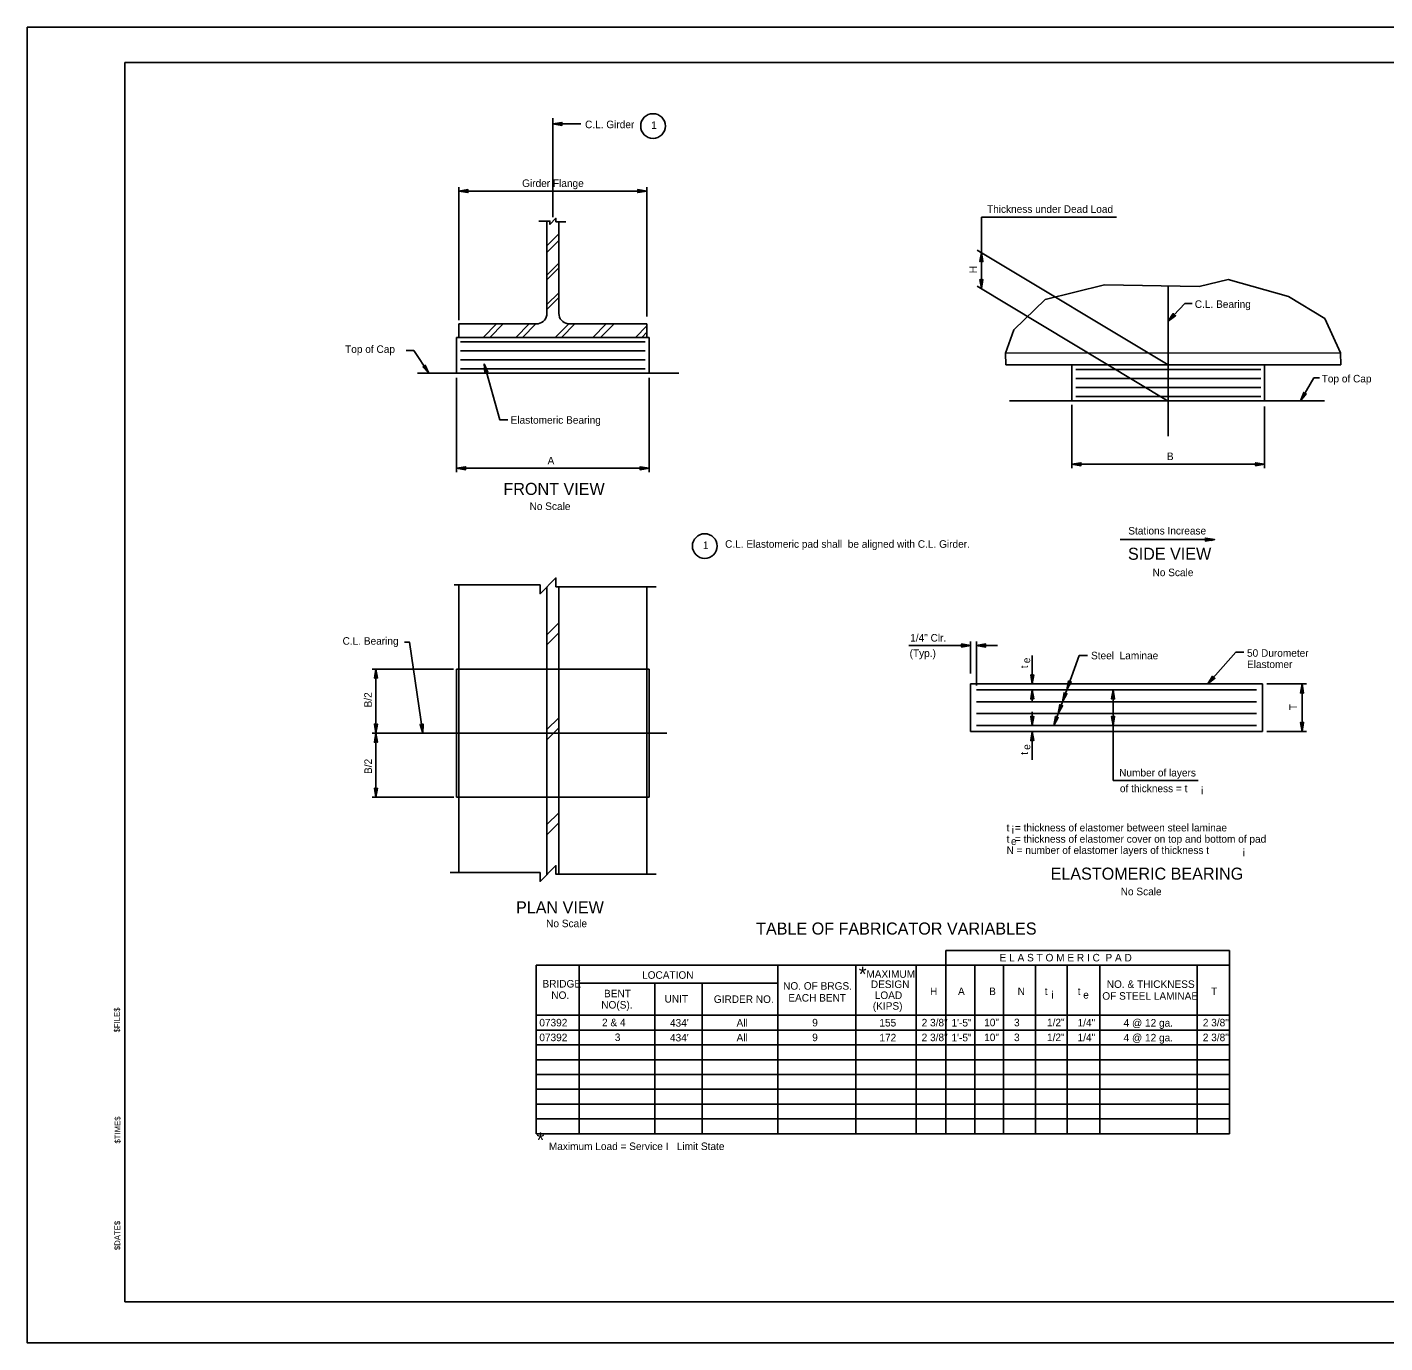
# Model space of a CAD drawing. Extents: x -193 to 149, y 507 to 725.
# Drawn here: x -192.5 to 32.6, y 507.1 to 725.2 of the extents above; entities that cross this region are included whole.
import ezdxf

# ---------------------------------------------------------------- set-up
doc = ezdxf.new("R2010")
doc.units = 0
for name, color, linetype in [('border', 7, 'Continuous'), ('Border 2660-Hwy18 - Level 62', 7, 'Continuous'), ('Dimensions', 7, 'Continuous'), ('Level 20', 7, 'Continuous'), ('Level 21', 7, 'Continuous'), ('Level 31', 7, 'Continuous'), ('Level 40', 7, 'Continuous'), ('Level 41', 7, 'Continuous'), ('Level 42', 7, 'Continuous'), ('Level 43', 7, 'Continuous'), ('Level 58', 7, 'Continuous')]:
    doc.layers.add(name, color=color, linetype=linetype)

# ---------------------------------------------------------------- blocks, each defined once
blk = doc.blocks.new('ARROW')
at = {"layer": 'Level 58'}
blk.add_lwpolyline([(-1.2, 0.251), (0, 0), (-1.2, -0.251), (-1.004, 0)], close=True, dxfattribs=at)

msp = doc.modelspace()

# ---------------------------------------------------------------- linework, layer by layer
at = {"layer": 'border'}
for p, q in [((-176.33, 719.31), (143.78, 719.31)), ((-176.33, 513.86), (-176.33, 719.31)), ((143.78, 513.86), (-176.33, 513.86))]:
    msp.add_line(p, q, dxfattribs=at)
at = {"layer": 'Border 2660-Hwy18 - Level 62'}
msp.add_lwpolyline([(-192.53, 725.17), (148.65, 725.17), (148.65, 507.07), (-192.53, 507.07)], close=True, dxfattribs=at)
at = {"layer": 'Dimensions'}
for p, q in [((-129.69, 671.58), (-128.41, 671.58)), ((-128.41, 671.58), (-125.92, 667.79))]:
    msp.add_line(p, q, dxfattribs=at)
msp.add_lwpolyline([(-125.92, 667.79), (-126.51, 669.12), (-126.64, 668.89), (-126.91, 668.86)], close=True, dxfattribs=at)
at = {"layer": 'Level 20'}
for p, q in [((-105.35, 693.67), (-105.35, 710.08)), ((-3.29, 657.38), (-3.29, 682.35)), ((-135.32, 608.13), (-86.47, 608.13))]:
    msp.add_line(p, q, dxfattribs=at)
at = {"layer": 'Level 21'}
for p, q in [((-84.47, 667.79), (-127.81, 667.79)), ((22.62, 663.21), (-29.62, 663.21))]:
    msp.add_line(p, q, dxfattribs=at)
at = {"layer": 'Level 31'}
for p, q in [((-106.33, 693.03), (-106.33, 677.74)), ((-104.36, 692.92), (-104.36, 677.74)), ((-107.8, 675.98), (-120.93, 675.98)), ((-120.93, 673.75), (-120.93, 675.98)), ((-102.89, 675.98), (-89.76, 675.98)), ((-89.76, 673.75), (-89.76, 675.98)), ((-121.33, 673.75), (-104.36, 673.75)), ((-121.33, 667.79), (-121.33, 673.75)), ((-89.37, 673.75), (-106.33, 673.75)), ((-89.37, 667.79), (-89.37, 673.75)), ((-120.68, 673.01), (-90.01, 673.01)), ((-120.68, 671.52), (-90.01, 671.52)), ((-30.3, 671.15), (25.29, 671.16)), ((-120.68, 670.02), (-90.01, 670.02)), ((-30.24, 669.17), (25.35, 669.19)), ((-19.27, 663.21), (-19.27, 669.17)), ((12.69, 663.21), (12.69, 669.17)), ((-120.68, 668.53), (-90.01, 668.53)), ((-18.62, 668.43), (12.05, 668.43)), ((-18.62, 666.94), (12.05, 666.94)), ((-18.62, 665.45), (12.05, 665.45)), ((-18.62, 663.95), (12.05, 663.95)), ((-120.93, 585.03), (-120.93, 632.7)), ((-106.33, 632.38), (-106.33, 584.69)), ((-104.36, 632.42), (-104.36, 584.74)), ((-89.76, 584.74), (-89.76, 632.42)), ((-121.33, 618.76), (-121.33, 597.5)), ((-120.93, 618.76), (-121.33, 618.76)), ((-120.93, 618.76), (-89.76, 618.76)), ((-89.76, 618.76), (-89.37, 618.76)), ((-89.37, 618.76), (-89.37, 597.5)), ((-36.07, 616.29), (12.33, 616.29)), ((-36.07, 616.29), (-36.07, 608.42)), ((-35.09, 615.31), (11.33, 615.31)), ((12.33, 616.29), (12.33, 608.42)), ((-35.09, 613.34), (-20.87, 613.34)), ((-20.87, 613.34), (11.33, 613.34)), ((-35.09, 611.37), (11.33, 611.37)), ((-36.07, 608.42), (12.33, 608.42)), ((-35.09, 609.4), (-22.31, 609.4)), ((-22.31, 609.4), (11.33, 609.4)), ((-120.93, 597.5), (-121.33, 597.5)), ((-120.93, 597.5), (-89.76, 597.5)), ((-89.76, 597.5), (-89.37, 597.5))]:
    msp.add_line(p, q, dxfattribs=at)
for centre, start, end in [((-108.1, 677.73), 279.5, 0), ((-102.59, 677.73), 180, 260.5)]:
    msp.add_arc(centre, 1.76, start, end, dxfattribs=at)
at = {"layer": 'Level 40'}
for p, q in [((-100.96, 569.66), (-100.96, 541.74)), ((-68.06, 569.66), (-68.06, 541.74)), ((-55.1, 569.66), (-55.1, 541.74)), ((-45.11, 569.66), (-45.11, 541.74)), ((-35.38, 569.66), (-35.38, 541.74)), ((-30.59, 569.66), (-30.59, 541.74)), ((-25.3, 569.66), (-25.3, 541.74)), ((-20.03, 569.66), (-20.03, 541.74)), ((-14.65, 569.66), (-14.65, 541.74)), ((1.49, 569.66), (1.49, 541.74)), ((-100.96, 566.68), (-68.06, 566.68)), ((-88.46, 566.68), (-88.46, 541.74)), ((-80.56, 566.68), (-80.56, 541.74)), ((-108.12, 561.37), (6.87, 561.37)), ((6.87, 561.87), (6.87, 558.38)), ((-108.12, 558.92), (6.87, 558.92)), ((-108.12, 556.46), (6.87, 556.46)), ((-108.12, 554.01), (6.87, 554.01)), ((-108.12, 551.56), (6.87, 551.56)), ((-108.12, 549.1), (6.87, 549.1)), ((-108.12, 546.65), (6.87, 546.65)), ((-108.12, 544.2), (6.87, 544.2))]:
    msp.add_line(p, q, dxfattribs=at)
for centre in [(-88.73, 708.78), (-80.15, 639.15)]:
    msp.add_circle(centre, 2.05, dxfattribs=at)
at = {"layer": 'Level 41'}
for p, q in [((-40.17, 572.11), (-40.17, 541.74)), ((-40.17, 572.11), (6.87, 572.11)), ((6.87, 572.11), (6.87, 541.74)), ((-108.12, 569.66), (6.87, 569.66)), ((-108.12, 569.66), (-108.12, 541.74)), ((-108.12, 541.74), (6.87, 541.74))]:
    msp.add_line(p, q, dxfattribs=at)
at = {"layer": 'Level 42'}
for p, q in [((-106.33, 688.92), (-104.36, 690.89)), ((-106.33, 687.82), (-104.36, 689.81)), ((-106.33, 684.07), (-104.36, 686.03)), ((-106.33, 683.3), (-104.36, 685.27)), ((-106.33, 679.18), (-104.36, 681.15)), ((-106.33, 678.37), (-104.36, 680.37)), ((-116.93, 673.75), (-114.7, 675.98)), ((-115.8, 673.75), (-113.57, 675.98)), ((-111.5, 673.75), (-109.28, 675.98)), ((-110.4, 673.75), (-108.18, 675.98)), ((-104.95, 673.75), (-102.71, 675.98)), ((-103.92, 673.75), (-101.69, 675.98)), ((-98.73, 673.75), (-96.52, 675.98)), ((-97.43, 673.75), (-95.2, 675.98)), ((-91.64, 673.75), (-89.76, 675.66)), ((-90.59, 673.75), (-89.76, 674.59)), ((-106.33, 624.46), (-104.36, 626.43)), ((-106.33, 622.79), (-104.36, 624.78)), ((-106.33, 608.72), (-104.36, 610.69)), ((-106.33, 607.04), (-104.36, 609.04)), ((-106.33, 592.98), (-104.36, 594.94)), ((-106.33, 591.3), (-104.36, 593.29))]:
    msp.add_line(p, q, dxfattribs=at)
at = {"layer": 'Level 43'}
for p, q in [((-100.7, 709.12), (-105.35, 709.12)), ((-120.93, 676.61), (-120.93, 698.64)), ((-89.76, 677.19), (-89.76, 698.64)), ((-120.93, 698), (-89.76, 698)), ((-11.84, 693.7), (-34.28, 693.7)), ((-34.28, 693.7), (-34.28, 691.97)), ((-34.28, 681.83), (-34.28, 691.97)), ((-3.29, 669.17), (-34.96, 688.23)), ((-3.29, 663.18), (-35, 682.26)), ((-121.33, 667.04), (-121.33, 651.4)), ((-89.37, 667.04), (-89.37, 651.4)), ((-19.27, 662.56), (-19.27, 652.06)), ((12.69, 662.31), (12.69, 652.06)), ((-121.33, 652.04), (-89.37, 652.04)), ((-19.27, 652.71), (12.69, 652.71)), ((-46.28, 622.67), (-36.07, 622.67)), ((-36.07, 618.02), (-36.07, 623.31)), ((-35.09, 616.05), (-35.09, 623.31)), ((-31.6, 622.67), (-35.09, 622.67)), ((-25.85, 621), (-25.85, 616.29)), ((-121.82, 618.76), (-135.32, 618.76)), ((-134.68, 608.13), (-134.68, 618.76)), ((-25.85, 615.31), (-25.85, 613.23)), ((-12.42, 607.44), (-12.42, 615.31)), ((13.06, 616.29), (19.66, 616.29)), ((18.91, 608.42), (18.91, 616.29)), ((-25.85, 609.4), (-25.85, 611.68)), ((-134.68, 597.5), (-134.68, 608.13)), ((-25.85, 603.73), (-25.85, 608.42)), ((13.06, 608.42), (19.66, 608.42)), ((-12.42, 607.44), (-12.42, 600.28)), ((-12.42, 600.28), (1.69, 600.28)), ((-121.79, 597.5), (-135.32, 597.5))]:
    msp.add_line(p, q, dxfattribs=at)
for points in [[(-105.35, 709.12), (-103.85, 708.87), (-103.98, 709.12), (-103.85, 709.37)], [(-120.93, 698), (-119.43, 697.75), (-119.56, 698), (-119.43, 698.25)], [(-89.76, 698), (-91.26, 698.25), (-91.13, 698), (-91.26, 697.75)], [(-34.28, 687.81), (-34.53, 686.31), (-34.28, 686.44), (-34.03, 686.31)], [(-34.28, 681.83), (-34.03, 683.33), (-34.28, 683.2), (-34.53, 683.33)], [(-3.29, 676.42), (-2.08, 677.34), (-2.35, 677.42), (-2.44, 677.68)], [(-116.74, 669.37), (-116.62, 667.86), (-116.41, 668.04), (-116.13, 667.98)], [(18.64, 663.21), (19.61, 664.37), (19.33, 664.39), (19.18, 664.63)], [(-121.33, 652.04), (-119.83, 651.79), (-119.96, 652.04), (-119.83, 652.29)], [(-89.37, 652.04), (-90.87, 652.29), (-90.74, 652.04), (-90.87, 651.79)], [(-19.27, 652.71), (-17.77, 652.46), (-17.9, 652.71), (-17.77, 652.96)], [(12.69, 652.71), (11.19, 652.96), (11.32, 652.71), (11.19, 652.46)], [(4.39, 640.22), (2.89, 640.47), (3.02, 640.22), (2.89, 639.97)], [(-36.07, 622.67), (-37.57, 622.92), (-37.44, 622.67), (-37.57, 622.42)], [(-35.09, 622.67), (-33.59, 622.42), (-33.72, 622.67), (-33.59, 622.92)], [(-134.68, 618.76), (-134.93, 617.26), (-134.68, 617.39), (-134.43, 617.26)], [(-25.85, 616.29), (-25.6, 617.79), (-25.85, 617.66), (-26.1, 617.79)], [(3.27, 616.29), (4.46, 617.25), (4.18, 617.32), (4.08, 617.58)], [(-25.85, 615.31), (-26.1, 613.81), (-25.85, 613.94), (-25.6, 613.81)], [(-20.84, 613.34), (-20.09, 614.66), (-20.37, 614.63), (-20.56, 614.83)], [(-20.12, 615.31), (-19.37, 616.63), (-19.65, 616.59), (-19.84, 616.8)], [(-12.42, 615.31), (-12.67, 613.81), (-12.42, 613.94), (-12.17, 613.81)], [(18.91, 616.29), (18.66, 614.79), (18.91, 614.92), (19.16, 614.79)], [(-21.56, 611.37), (-20.81, 612.69), (-21.09, 612.66), (-21.28, 612.87)], [(-25.85, 609.4), (-25.6, 610.9), (-25.85, 610.77), (-26.1, 610.9)], [(-22.28, 609.4), (-21.53, 610.73), (-21.81, 610.69), (-22, 610.9)], [(-12.42, 609.4), (-12.17, 610.9), (-12.42, 610.77), (-12.67, 610.9)], [(-134.68, 608.13), (-134.43, 609.63), (-134.68, 609.5), (-134.93, 609.63)], [(-134.68, 608.13), (-134.93, 606.63), (-134.68, 606.76), (-134.43, 606.63)], [(-126.9, 608.13), (-126.87, 609.65), (-127.09, 609.49), (-127.36, 609.58)], [(-25.85, 608.42), (-26.1, 606.92), (-25.85, 607.05), (-25.6, 606.92)], [(18.91, 608.42), (19.16, 609.92), (18.91, 609.79), (18.66, 609.92)], [(-134.68, 597.5), (-134.43, 599), (-134.68, 598.87), (-134.93, 599)]]:
    msp.add_lwpolyline(points, close=True, dxfattribs=at)
for points in [[(-107.66, 693.03), (-105.84, 693.03), (-105.84, 692.48), (-104.83, 693.49), (-104.83, 692.92), (-103.19, 692.92)], [(-30.24, 669.17), (-30.3, 671.13), (-28.92, 674.99), (-23.67, 680.04), (-13.85, 682.48), (1.87, 682.19), (6.66, 683.36), (16.66, 680.5), (22.71, 676.85), (25.29, 671.16), (25.35, 669.19)], [(0.68, 679.37), (-0.51, 679.37), (-3.29, 676.42)], [(-116.74, 669.37), (-114.12, 660.07), (-112.81, 660.06)], [(21.79, 667.02), (20.88, 667.02), (18.64, 663.21)], [(-11.26, 640.22), (4.39, 640.22)], [(-121.72, 632.7), (-107.46, 632.7), (-107.46, 631.26), (-104.83, 633.87), (-104.83, 632.42), (-88.23, 632.42)], [(-129.95, 623.21), (-129.11, 623.21), (-126.9, 608.13)], [(3.27, 616.29), (7.92, 621.54), (9.26, 621.54)], [(-20.12, 615.31), (-18.03, 621.01), (-16.69, 621.01)], [(-20.84, 613.34), (-20.12, 615.31)], [(-21.56, 611.37), (-20.84, 613.34)], [(-22.28, 609.4), (-21.56, 611.37)], [(-122.39, 585.03), (-107.46, 585.03), (-107.46, 583.57), (-104.83, 586.18), (-104.83, 584.74), (-88.23, 584.74)]]:
    msp.add_lwpolyline(points, dxfattribs=at)

# ---------------------------------------------------------------- block references
at = {"layer": 'Level 43', "xscale": 0.5247989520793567, "yscale": 0.5247989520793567}
msp.add_blockref('ARROW', (4.39, 640.22), dxfattribs=at)

# ---------------------------------------------------------------- texts
at = {"layer": 'border'}
for s, p in [('$FILE$', (-177.16, 558.52)), ('$TIME$', (-177.06, 540.11)), ('$DATE$', (-177.1, 522.44))]:
    msp.add_text(s, height=0.96, rotation=89.9999, dxfattribs=at).set_placement(p)
at = {"layer": 'Level 40'}
for s, height, p in [('C.L. Girder', 1.25, (-100.01, 708.42)), ('1', 1.25, (-89.04, 708.3)), ('Girder Flange', 1.25, (-110.44, 698.68)), ('Thickness under Dead Load', 1.25, (-33.34, 694.39)), ('C.L. Bearing', 1.25, (1.12, 678.63)), ('Top of Cap', 1.25, (-139.8, 671.17)), ('Top of Cap', 1.25, (22.16, 666.28)), ('Elastomeric Bearing', 1.25, (-112.35, 659.43)), ('A', 1.25, (-106.22, 652.69)), ('B', 1.25, (-3.51, 653.41)), ('No Scale', 1.25, (-109.21, 645.13)), ('Stations Increase', 1.25, (-9.91, 641.07)), ('1', 1.25, (-80.46, 638.66)), ('C.L. Elastomeric pad shall  be aligned with C.L. Girder.', 1.25, (-76.78, 638.87)), ('No Scale', 1.25, (-5.89, 634.16)), ('C.L. Bearing', 1.25, (-140.22, 622.8)), ('1/4" Clr.', 1.25, (-46.08, 623.32)), ('(Typ.)', 1.25, (-46.18, 620.77)), ('Steel  Laminae', 1.25, (-16.09, 620.38)), ('50 Durometer', 1.25, (9.78, 620.8)), ('Elastomer', 1.25, (9.78, 618.93)), ('Number of layers', 1.25, (-11.42, 600.96)), ('of thickness = t', 1.25, (-11.3, 598.35)), ('i', 1.25, (2.17, 597.99)), ('t  = thickness of elastomer between steel laminae', 1.25, (-30.1, 591.85)), ('i', 1.25, (-29.24, 591.47)), ('t  = thickness of elastomer cover on top and bottom of pad', 1.25, (-30.1, 589.98)), ('e', 1.25, (-29.36, 589.6)), ('N = number of elastomer layers of thickness t', 1.25, (-30.1, 588.12)), ('i', 1.25, (9.07, 587.72)), ('No Scale', 1.25, (-11.17, 581.27)), ('No Scale', 1.25, (-106.46, 575.97)), ('E L A S T O M E R I C  P A D', 1.25, (-31.25, 570.3)), ('LOCATION', 1.25, (-90.55, 567.42)), ('*', 2.5, (-54.62, 566.95)), ('MAXIMUM', 1.25, (-53.35, 567.59)), ('BRIDGE', 1.25, (-107.07, 565.97)), ('NO.', 1.25, (-105.6, 564.08)), ('BENT', 1.25, (-96.86, 564.35)), ('NO. OF BRGS.', 1.25, (-67.16, 565.61)), ('DESIGN', 1.25, (-52.61, 565.89)), ('LOAD', 1.25, (-51.96, 564.07)), ('H', 1.25, (-42.79, 564.72)), ('A', 1.25, (-38.15, 564.72)), ('B', 1.25, (-32.99, 564.72)), ('N', 1.25, (-28.26, 564.72)), ('t ', 1.25, (-23.76, 564.72)), ('i', 1.25, (-22.65, 564.14)), ('t ', 1.25, (-18.29, 564.72)), ('OF STEEL LAMINAE', 1.25, (-14.22, 563.95)), ('NO. & THICKNESS', 1.25, (-13.48, 565.91)), ('T', 1.25, (3.83, 564.72)), ('NO(S).', 1.25, (-97.32, 562.48)), ('UNIT', 1.25, (-86.82, 563.48)), ('GIRDER NO.', 1.25, (-78.65, 563.42)), ('EACH BENT', 1.25, (-66.29, 563.64)), ('(KIPS)', 1.25, (-52.28, 562.29)), ('e', 1.25, (-17.38, 564.14)), ('07392', 1.25, (-107.59, 559.53)), ('2 & 4', 1.25, (-97.19, 559.56)), ("434'", 1.25, (-85.92, 559.49)), ('All', 1.25, (-74.88, 559.49)), ('9', 1.25, (-62.33, 559.53)), ('155', 1.25, (-51.19, 559.51)), ('2 3/8"', 1.25, (-44.18, 559.53)), ('1\'-5"', 1.25, (-39.23, 559.51)), ('10"', 1.25, (-33.81, 559.55)), ('3', 1.25, (-28.86, 559.55)), ('1/2"', 1.25, (-23.39, 559.55)), ('1/4"', 1.25, (-18.32, 559.52)), ('4 @ 12 ga.', 1.25, (-10.69, 559.49)), ('2 3/8"', 1.25, (2.45, 559.53)), ('07392', 1.25, (-107.59, 557.08)), ('3', 1.25, (-95.07, 557.1)), ("434'", 1.25, (-85.92, 557.04)), ('All', 1.25, (-74.88, 557.04)), ('9', 1.25, (-62.33, 557.08)), ('172', 1.25, (-51.19, 557.05)), ('2 3/8"', 1.25, (-44.18, 557.08)), ('1\'-5"', 1.25, (-39.23, 557.05)), ('10"', 1.25, (-33.81, 557.09)), ('3', 1.25, (-28.86, 557.09)), ('1/2"', 1.25, (-23.39, 557.09)), ('1/4"', 1.25, (-18.32, 557.07)), ('4 @ 12 ga.', 1.25, (-10.69, 557.04)), ('2 3/8"', 1.25, (2.45, 557.08)), ('*', 2.5, (-108.05, 539.44)), ('Maximum Load = Service I   Limit State', 1.25, (-106.01, 539.03))]:
    msp.add_text(s, height=height, dxfattribs=at).set_placement(p)
for s, p in [('H', (-35.02, 684.37)), ('t', (-26.55, 618.9)), ('e', (-26.18, 619.73)), ('B/2', (-135.38, 612.41)), ('T', (18.06, 611.96)), ('e', (-26.16, 605.37)), ('B/2', (-135.35, 601.37)), ('t', (-26.53, 604.55))]:
    msp.add_text(s, height=1.25, rotation=90, dxfattribs=at).set_placement(p)
at = {"layer": 'Level 41'}
for s, p in [(' FRONT VIEW ', (-114.28, 647.63)), (' SIDE VIEW ', (-10.71, 636.88)), (' ELASTOMERIC BEARING ', (-23.54, 583.85)), (' PLAN VIEW ', (-112.2, 578.26)), (' TABLE OF FABRICATOR VARIABLES ', (-72.38, 574.75))]:
    msp.add_text(s, height=2, dxfattribs=at).set_placement(p)

doc.saveas('drawing.dxf')
